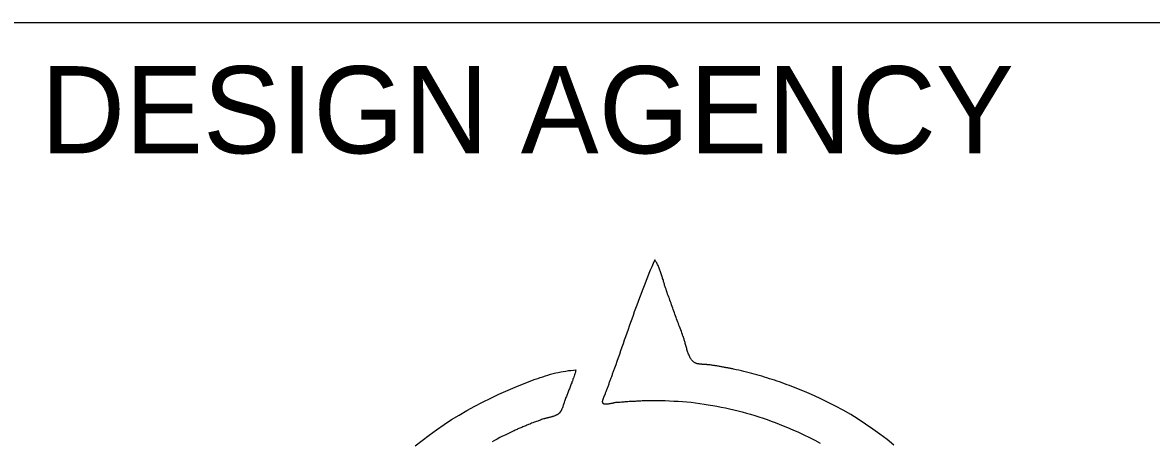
# Model space of a CAD drawing. Extents: x 0 to 34, y 0 to 22.
# Drawn here: x 32.029 to 33.322, y 4.021 to 4.5 of the extents above; entities that cross this region are included whole.
import ezdxf

# ---------------------------------------------------------------- set-up
doc = ezdxf.new("R2010")
doc.units = 0
for name, color, linetype in [('SH_Border', 7, 'Continuous'), ('SH_Data', 7, 'Continuous'), ('SH_Text', 7, 'Continuous')]:
    doc.layers.add(name, color=color, linetype=linetype)

msp = doc.modelspace()

# ---------------------------------------------------------------- linework, layer by layer
at = {"layer": 'SH_Border'}
msp.add_line((32, 4.5), (33.5, 4.5), dxfattribs=at)
at = {"layer": 'SH_Text'}
for points in [[(32.7532, 4.2277), (32.7515, 4.2238), (32.7498, 4.2199), (32.7481, 4.216), (32.7466, 4.212), (32.745, 4.208), (32.7434, 4.2041), (32.7418, 4.2001), (32.7403, 4.1961), (32.7387, 4.1921), (32.7372, 4.1881), (32.7357, 4.1841), (32.7342, 4.1801), (32.7328, 4.176), (32.7313, 4.172), (32.7298, 4.168), (32.7284, 4.1639), (32.7271, 4.1599), (32.7256, 4.1558), (32.7241, 4.1518), (32.7227, 4.1478), (32.7214, 4.1436), (32.7199, 4.1396), (32.7184, 4.1355), (32.7171, 4.1315), (32.7157, 4.1275), (32.7142, 4.1235), (32.7129, 4.1194), (32.7114, 4.1154), (32.71, 4.1114), (32.7085, 4.1074), (32.707, 4.1035)], [(32.7656, 4.1959), (32.7652, 4.1969), (32.7649, 4.1978), (32.7646, 4.1988), (32.7643, 4.1998), (32.764, 4.2009), (32.7637, 4.202), (32.7633, 4.2031), (32.7631, 4.2041), (32.7627, 4.2051), (32.7623, 4.2063), (32.7621, 4.2074), (32.7617, 4.2085), (32.7614, 4.2096), (32.761, 4.2107), (32.7606, 4.2118), (32.7603, 4.2129), (32.7599, 4.214), (32.7595, 4.2151), (32.7592, 4.2161), (32.7587, 4.2172), (32.7583, 4.2182), (32.7578, 4.2193), (32.7575, 4.2203), (32.757, 4.2214), (32.7565, 4.2223), (32.756, 4.2233), (32.7555, 4.2242), (32.7549, 4.2251), (32.7545, 4.226), (32.7538, 4.2268), (32.7532, 4.2277)], [(32.7856, 4.1404), (32.785, 4.1422), (32.7844, 4.144), (32.7837, 4.1457), (32.7831, 4.1475), (32.7823, 4.1493), (32.7817, 4.1512), (32.781, 4.1529), (32.7804, 4.1547), (32.7797, 4.1565), (32.7791, 4.1582), (32.7783, 4.16), (32.7777, 4.1618), (32.777, 4.1637), (32.7764, 4.1654), (32.7758, 4.1672), (32.7751, 4.169), (32.7745, 4.1708), (32.7739, 4.1725), (32.7731, 4.1743), (32.7725, 4.1761), (32.7719, 4.178), (32.7712, 4.1797), (32.7706, 4.1815), (32.77, 4.1833), (32.7694, 4.1851), (32.7686, 4.1869), (32.768, 4.1886), (32.7674, 4.1904), (32.7668, 4.1923), (32.7662, 4.1941), (32.7656, 4.1959)], [(32.7979, 4.1106), (32.7973, 4.1112), (32.7966, 4.1118), (32.796, 4.1124), (32.7954, 4.1131), (32.7949, 4.1138), (32.7943, 4.1147), (32.7939, 4.1156), (32.7934, 4.1165), (32.7929, 4.1175), (32.7925, 4.1186), (32.792, 4.1195), (32.7917, 4.1206), (32.7913, 4.1217), (32.7908, 4.1228), (32.7905, 4.1239), (32.7901, 4.1251), (32.7899, 4.1262), (32.7895, 4.1274), (32.7891, 4.1285), (32.7889, 4.1296), (32.7885, 4.1308), (32.7882, 4.1319), (32.7879, 4.133), (32.7877, 4.1341), (32.7873, 4.135), (32.7871, 4.136), (32.7868, 4.137), (32.7865, 4.138), (32.7862, 4.1388), (32.786, 4.1396), (32.7856, 4.1404)], [(32.5747, 4.0736), (32.5772, 4.0747), (32.5799, 4.0759), (32.5825, 4.077), (32.5852, 4.0782), (32.5879, 4.0794), (32.5907, 4.0806), (32.5934, 4.0818), (32.5962, 4.0829), (32.599, 4.0841), (32.6018, 4.0853), (32.6047, 4.0864), (32.6075, 4.0876), (32.6104, 4.0887), (32.6133, 4.0898), (32.6162, 4.0909), (32.6192, 4.0919), (32.6221, 4.093), (32.6251, 4.0938), (32.628, 4.0948), (32.6309, 4.0956), (32.6338, 4.0965), (32.6369, 4.0973), (32.6398, 4.0981), (32.6427, 4.0987), (32.6456, 4.0993), (32.6485, 4.0998), (32.6514, 4.1002), (32.6543, 4.1007), (32.6572, 4.101), (32.6601, 4.1012), (32.6629, 4.1015)], [(32.6629, 4.1015), (32.6626, 4.1002), (32.6623, 4.0992), (32.6619, 4.0979), (32.6616, 4.0969), (32.6612, 4.0958), (32.6609, 4.0945), (32.6605, 4.0935), (32.6601, 4.0922), (32.6596, 4.0912), (32.6593, 4.0901), (32.6589, 4.0888), (32.6584, 4.0878), (32.6581, 4.0867), (32.6576, 4.0856), (32.6572, 4.0844), (32.6567, 4.0833), (32.6564, 4.0822), (32.6559, 4.0811), (32.6555, 4.0799), (32.655, 4.0788), (32.6546, 4.0777), (32.6542, 4.0766), (32.6537, 4.0754), (32.6532, 4.0743), (32.6529, 4.0732), (32.6524, 4.0721), (32.652, 4.071), (32.6515, 4.0698), (32.6512, 4.0687), (32.6507, 4.0676), (32.6503, 4.0665)], [(32.707, 4.1035), (32.7067, 4.1025), (32.7063, 4.1016), (32.7061, 4.1006), (32.7057, 4.0996), (32.7054, 4.0987), (32.705, 4.0977), (32.7046, 4.0967), (32.7043, 4.0958), (32.7039, 4.0948), (32.7037, 4.0938), (32.7033, 4.0928), (32.7029, 4.092), (32.7026, 4.091), (32.7022, 4.0901), (32.7018, 4.0891), (32.7015, 4.0881), (32.7011, 4.0872), (32.7007, 4.0862), (32.7005, 4.0852), (32.7001, 4.0842), (32.6998, 4.0833), (32.6994, 4.0823), (32.699, 4.0813), (32.6987, 4.0804), (32.6983, 4.0795), (32.698, 4.0785), (32.6976, 4.0776), (32.6972, 4.0766), (32.6969, 4.0756), (32.6965, 4.0747), (32.6963, 4.0737)], [(32.8139, 4.1075), (32.8134, 4.1075), (32.8129, 4.1076), (32.8124, 4.1076), (32.8119, 4.1076), (32.8114, 4.1078), (32.8108, 4.1078), (32.8103, 4.1078), (32.8097, 4.1078), (32.8093, 4.1079), (32.8086, 4.1079), (32.808, 4.1079), (32.8076, 4.1079), (32.807, 4.108), (32.8063, 4.108), (32.8059, 4.1081), (32.8053, 4.1081), (32.8046, 4.1082), (32.8042, 4.1082), (32.8036, 4.1084), (32.8031, 4.1085), (32.8025, 4.1086), (32.802, 4.1087), (32.8015, 4.1089), (32.8009, 4.109), (32.8004, 4.1092), (32.7999, 4.1093), (32.7996, 4.1096), (32.7991, 4.1098), (32.7986, 4.1101), (32.7982, 4.1103), (32.7979, 4.1106)], [(32.8436, 4.1024), (32.8426, 4.1027), (32.8417, 4.1028), (32.8408, 4.103), (32.8398, 4.1033), (32.8388, 4.1034), (32.8379, 4.1036), (32.8369, 4.1038), (32.8359, 4.104), (32.835, 4.1041), (32.8341, 4.1044), (32.8331, 4.1045), (32.8322, 4.1047), (32.8312, 4.1049), (32.8302, 4.1051), (32.8293, 4.1052), (32.8283, 4.1055), (32.8273, 4.1056), (32.8263, 4.1057), (32.8254, 4.1059), (32.8244, 4.1061), (32.8234, 4.1062), (32.8225, 4.1063), (32.8215, 4.1065), (32.8205, 4.1067), (32.8196, 4.1068), (32.8186, 4.1069), (32.8177, 4.107), (32.8168, 4.1072), (32.8158, 4.1073), (32.8148, 4.1074), (32.8139, 4.1075)], [(32.9329, 4.0732), (32.9301, 4.0744), (32.9273, 4.0756), (32.9246, 4.0768), (32.9216, 4.0781), (32.9189, 4.0791), (32.9161, 4.0802), (32.9133, 4.0815), (32.9104, 4.0825), (32.9076, 4.0835), (32.9048, 4.0846), (32.9019, 4.0857), (32.8991, 4.0867), (32.8962, 4.0878), (32.8933, 4.0887), (32.8905, 4.0897), (32.8876, 4.0907), (32.8847, 4.0915), (32.8818, 4.0925), (32.8788, 4.0933), (32.8759, 4.0943), (32.873, 4.0952), (32.8701, 4.096), (32.8672, 4.0967), (32.8643, 4.0976), (32.8614, 4.0983), (32.8584, 4.099), (32.8554, 4.0998), (32.8525, 4.1005), (32.8495, 4.1012), (32.8466, 4.1018), (32.8436, 4.1024)], [(32.4788, 4.0143), (32.4868, 4.0207), (32.495, 4.0269), (32.5034, 4.033), (32.5119, 4.0388), (32.5205, 4.0445), (32.5292, 4.0498), (32.538, 4.055), (32.547, 4.06), (32.5561, 4.0647), (32.5653, 4.0693), (32.5747, 4.0736)], [(32.6963, 4.0737), (32.6961, 4.0735), (32.696, 4.0732), (32.6959, 4.073), (32.6958, 4.0727), (32.6957, 4.0724), (32.6955, 4.0721), (32.6954, 4.0718), (32.6952, 4.0714), (32.695, 4.071), (32.6949, 4.0707), (32.6947, 4.0703), (32.6946, 4.0699), (32.6944, 4.0696), (32.6942, 4.0691), (32.6941, 4.0687), (32.694, 4.0684), (32.6938, 4.068), (32.6937, 4.0675), (32.6936, 4.0671), (32.6935, 4.0668), (32.6935, 4.0664), (32.6933, 4.0661), (32.6933, 4.0657), (32.6932, 4.0653), (32.6932, 4.065), (32.6932, 4.0647), (32.6933, 4.0644), (32.6933, 4.0641), (32.6935, 4.0639), (32.6936, 4.0636), (32.6937, 4.0634)], [(33.0272, 4.0154), (33.0194, 4.0217), (33.0112, 4.0277), (33.0031, 4.0337), (32.9947, 4.0394), (32.9863, 4.045), (32.9777, 4.0503), (32.9689, 4.0553), (32.9601, 4.0601), (32.9511, 4.0647), (32.942, 4.0691), (32.9329, 4.0732)], [(32.6503, 4.0665), (32.6501, 4.0661), (32.6499, 4.0656), (32.6498, 4.0652), (32.6496, 4.0647), (32.6495, 4.0642), (32.6493, 4.0638), (32.6492, 4.0631), (32.649, 4.0627), (32.6489, 4.0622), (32.6487, 4.0617), (32.6485, 4.0611), (32.6484, 4.0606), (32.6481, 4.0601), (32.648, 4.0595), (32.6478, 4.059), (32.6476, 4.0585), (32.6474, 4.0579), (32.6473, 4.0574), (32.647, 4.057), (32.6468, 4.0565), (32.6466, 4.056), (32.6463, 4.0555), (32.6461, 4.055), (32.6458, 4.0545), (32.6456, 4.0542), (32.6453, 4.0537), (32.6451, 4.0533), (32.6447, 4.053), (32.6445, 4.0525), (32.6441, 4.0521), (32.6438, 4.0519)], [(32.6937, 4.0634), (32.694, 4.0633), (32.6942, 4.063), (32.6946, 4.0629), (32.6949, 4.0628), (32.6954, 4.0627), (32.6958, 4.0627), (32.6963, 4.0625), (32.6967, 4.0625), (32.6973, 4.0625), (32.6978, 4.0625), (32.6984, 4.0625), (32.699, 4.0627), (32.6997, 4.0627), (32.7003, 4.0628), (32.7009, 4.0629), (32.7015, 4.063), (32.7021, 4.063), (32.7027, 4.0631), (32.7033, 4.0633), (32.7039, 4.0634), (32.7045, 4.0635), (32.705, 4.0636), (32.7056, 4.0638), (32.7062, 4.0639), (32.7067, 4.064), (32.7072, 4.0641), (32.7077, 4.0641), (32.708, 4.0642), (32.7085, 4.0644), (32.7087, 4.0644), (32.7091, 4.0644)], [(32.7091, 4.0644), (32.7106, 4.0645), (32.7121, 4.0646), (32.7136, 4.0647), (32.7151, 4.0648), (32.7166, 4.065), (32.7181, 4.0651), (32.7195, 4.0652), (32.721, 4.0653), (32.7226, 4.0654), (32.724, 4.0656), (32.7255, 4.0657), (32.7269, 4.0657), (32.7285, 4.0658), (32.73, 4.0659), (32.7314, 4.0659), (32.7329, 4.0661), (32.7344, 4.0661), (32.7359, 4.0662), (32.7374, 4.0662), (32.7388, 4.0663), (32.7404, 4.0663), (32.7418, 4.0663), (32.7433, 4.0664), (32.7449, 4.0664), (32.7463, 4.0664), (32.7478, 4.0664), (32.7494, 4.0665), (32.7508, 4.0665), (32.7523, 4.0665), (32.7538, 4.0665), (32.7553, 4.0665)], [(32.7553, 4.0665), (32.7603, 4.0665), (32.7652, 4.0664), (32.7702, 4.0662), (32.7752, 4.0659), (32.7802, 4.0657), (32.785, 4.0653), (32.79, 4.0648), (32.7949, 4.0644), (32.7999, 4.0638), (32.8048, 4.0631), (32.8097, 4.0624), (32.8146, 4.0617), (32.8196, 4.0608), (32.8244, 4.06), (32.8293, 4.059), (32.8341, 4.0581), (32.839, 4.057), (32.8438, 4.0558), (32.8487, 4.0547), (32.8534, 4.0533), (32.8582, 4.052), (32.863, 4.0507), (32.8678, 4.0492), (32.8725, 4.0477), (32.8773, 4.0462), (32.882, 4.0446), (32.8866, 4.0429), (32.8913, 4.0412), (32.8959, 4.0394), (32.9005, 4.0376), (32.9052, 4.0357)], [(32.6438, 4.0519), (32.6434, 4.0515), (32.6429, 4.0511), (32.6424, 4.0508), (32.6421, 4.0505), (32.6415, 4.0502), (32.641, 4.0499), (32.6405, 4.0497), (32.6399, 4.0493), (32.6393, 4.0491), (32.6387, 4.0488), (32.6381, 4.0487), (32.6375, 4.0485), (32.6369, 4.0482), (32.6362, 4.0481), (32.6356, 4.0479), (32.635, 4.0476), (32.6343, 4.0475), (32.6337, 4.0474), (32.6331, 4.0471), (32.6324, 4.047), (32.6318, 4.0469), (32.6312, 4.0467), (32.6305, 4.0465), (32.6299, 4.0464), (32.6293, 4.0463), (32.6287, 4.0461), (32.6281, 4.0459), (32.6275, 4.0458), (32.627, 4.0456), (32.6264, 4.0454), (32.6259, 4.0453)], [(32.6259, 4.0453), (32.6248, 4.045), (32.6236, 4.0445), (32.6225, 4.0441), (32.6213, 4.0437), (32.6202, 4.0433), (32.6192, 4.0429), (32.6179, 4.0425), (32.6168, 4.0421), (32.6156, 4.0417), (32.6145, 4.0412), (32.6135, 4.0407), (32.6122, 4.0404), (32.6111, 4.0399), (32.6101, 4.0394), (32.6088, 4.039), (32.6078, 4.0385), (32.6067, 4.038), (32.6055, 4.0376), (32.6044, 4.0372), (32.6033, 4.0367), (32.6022, 4.0362), (32.601, 4.0357), (32.5999, 4.0353), (32.5988, 4.0348), (32.5977, 4.0343), (32.5966, 4.0338), (32.5955, 4.0333), (32.5944, 4.0328), (32.5932, 4.0324), (32.5921, 4.0317), (32.591, 4.0313)], [(32.9052, 4.0357), (32.9116, 4.033), (32.9179, 4.0302), (32.9242, 4.0271), (32.9305, 4.0241), (32.9367, 4.0208), (32.9427, 4.0174)], [(32.591, 4.0313), (32.588, 4.0299), (32.585, 4.0284), (32.5819, 4.0269), (32.5789, 4.0254), (32.5759, 4.0239), (32.5728, 4.0223), (32.5698, 4.0207), (32.5669, 4.0191)]]:
    msp.add_lwpolyline(points, dxfattribs=at)

# ---------------------------------------------------------------- texts
at = {"layer": 'SH_Data'}
msp.add_text('DESIGN AGENCY', height=0.1, dxfattribs=at).set_placement((32.05, 4.35))

doc.saveas('drawing.dxf')
